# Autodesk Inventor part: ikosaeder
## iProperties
Created: 2007-01
Part Number: ikosaeder
Cost Center: 0,13 kg
Material: S235JRG2 (1.0038)
Document SubType Name: Modeling
Designer: M. Fiedler
Manufacturer: Standard
Standards Organization: Custom
Einheit: Stück
Ersatzteil: ET AB VT
Grundoberfläche: Rz6.3
WSK a+: 0
WSK a-: -0.1
WSK i+: +0.1
WSK i-: 0
a: 52,533 mm
SaveDate: 2007-01-24
SaveTime: 23:08
FileName: ikosaeder
Masse: 0,13 kg
Author: M. Fiedler
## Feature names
1. Drehung1 [Revolution]
2. Drehung2 [Revolution]
3. Spiegeln1 [Mirror]
